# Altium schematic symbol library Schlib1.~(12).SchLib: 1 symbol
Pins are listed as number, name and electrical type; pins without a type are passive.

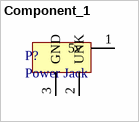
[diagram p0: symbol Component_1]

## Component_1
designator P?, comment Power Jack
footprint PCBComponent_1
pins: 1 5v, 2 UNK (power), 3 GND (power)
